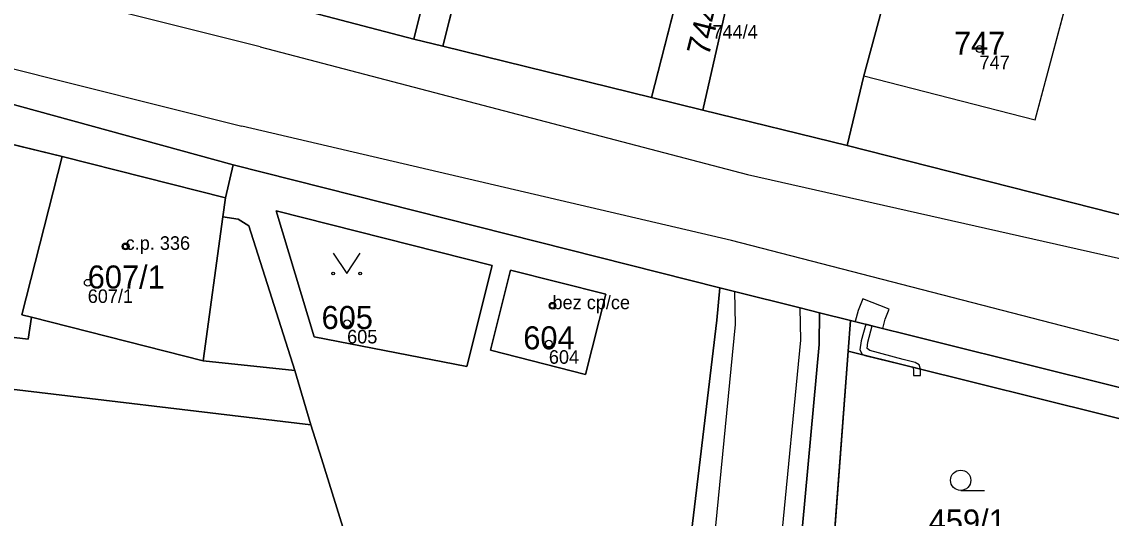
# Model space of a CAD drawing. Extents: x -603967 to -594699, y -1179315 to -1165625.
# Drawn here: x -598248.8 to -598168.4, y -1172272.3 to -1172235.7 of the extents above; entities that cross this region are included whole.
import ezdxf

# ---------------------------------------------------------------- set-up
doc = ezdxf.new("R2010")
doc.units = 0
for name, color, linetype in [('Definiční body', 7, 'Continuous'), ('Hranice parcel', 7, 'Continuous'), ('Parcelní čísla', 7, 'Continuous'), ('Polygon budovy', 7, 'Continuous'), ('Polygon parcely', 7, 'Continuous'), ('Vnitřní kresba', 7, 'Continuous'), ('Věcná břemena k části', 7, 'Continuous'), ('Značky budov', 7, 'Continuous'), ('Značky kultur', 7, 'Continuous')]:
    doc.layers.add(name, color=color, linetype=linetype)

msp = doc.modelspace()

# ---------------------------------------------------------------- linework, layer by layer
at = {"layer": 'Definiční body'}
for centre in [(-598178.09, -1172237.65994), (-598241.16, -1172252.22994), (-598243.96, -1172254.90994), (-598209.63, -1172256.60994), (-598224.8, -1172257.89994), (-598209.9, -1172259.39994)]:
    msp.add_circle(centre, 0.25, dxfattribs=at)
at = {"layer": 'Hranice parcel'}
for p, q in [((-598198.8, -1172227.49), (-598202.31, -1172241.23)), ((-598198.53, -1172242.16), (-598195.39, -1172228.4)), ((-598215.91, -1172230.22), (-598217.72, -1172237.46)), ((-598219.87, -1172236.93), (-598230.62, -1172234.12)), ((-598217.72, -1172237.46), (-598219.87, -1172236.93)), ((-598217.72, -1172237.46), (-598202.31, -1172241.23)), ((-598202.31, -1172241.23), (-598198.53, -1172242.16)), ((-598198.53, -1172242.16), (-598187.86, -1172244.77)), ((-598253.86, -1172243.64), (-598245.84, -1172245.6)), ((-598187.86, -1172244.77), (-598166.74, -1172250.14)), ((-598245.84, -1172245.6), (-598233.78, -1172248.64)), ((-598233.22, -1172246.2), (-598233.78, -1172248.64)), ((-598197.27, -1172255.28), (-598233.22, -1172246.2)), ((-598232.84, -1172250.21), (-598232.07, -1172250.7)), ((-598232.07, -1172250.7), (-598228.67, -1172261.38)), ((-598248.11, -1172257.46), (-598235.44, -1172260.68)), ((-598187.62, -1172257.69), (-598189.9, -1172257.12)), ((-598187.62, -1172257.69), (-598187.79, -1172259.97)), ((-598187.79, -1172259.97), (-598189.27, -1172279.58)), ((-598187.79, -1172259.97), (-598164.23, -1172265.81)), ((-598235.44, -1172260.68), (-598228.67, -1172261.38)), ((-598228.67, -1172261.38), (-598227.48, -1172265.39))]:
    msp.add_line(p, q, dxfattribs=at)
for points in [[(-598187.86, -1172244.77), (-598186.64, -1172239.63), (-598184.27, -1172230.87), (-598173.17, -1172211.68)], [(-598233.22, -1172246.2), (-598262.22, -1172238.25), (-598295.58, -1172230.95), (-598329.07, -1172222.19), (-598354.13, -1172216.53)], [(-598219.87, -1172236.93), (-598218.56, -1172231.67), (-598218.05, -1172229.68), (-598216.3, -1172222.79), (-598214.82, -1172220.18)], [(-598245.84, -1172245.6), (-598248.83, -1172257.28), (-598248.11, -1172257.46)], [(-598233.78, -1172248.64), (-598233.97, -1172250.05), (-598232.84, -1172250.21)], [(-598215.97, -1172261.09), (-598227.24, -1172258.89), (-598230.03, -1172249.59), (-598214.08, -1172253.64), (-598215.97, -1172261.09)], [(-598207.2, -1172261.67), (-598214.21, -1172259.88), (-598212.73, -1172253.99), (-598205.7, -1172255.75), (-598207.2, -1172261.67)], [(-598197.27, -1172255.28), (-598197.5, -1172257.68), (-598202.71, -1172301.27), (-598203.09, -1172311.78), (-598203.76, -1172315.82), (-598204.5, -1172318.52), (-598208.6, -1172325.98)], [(-598189.9, -1172257.12), (-598191.35, -1172256.76), (-598196.2, -1172255.55), (-598197.27, -1172255.28)], [(-598248.11, -1172257.46), (-598248.35, -1172259.08), (-598257.14, -1172258.05)], [(-598189.9, -1172257.12), (-598189.93, -1172259.47), (-598193.86, -1172302.03), (-598194.9, -1172313.74), (-598196.17, -1172318.03), (-598197.64, -1172321.62), (-598200.11, -1172325.95)], [(-598133.67, -1172271.05), (-598168.04, -1172262.57), (-598187.62, -1172257.69)], [(-598227.48, -1172265.39), (-598252.29, -1172262.45), (-598264.39, -1172261.06), (-598272.47, -1172262.37)], [(-598215.97, -1172302.17), (-598217.18, -1172298.45), (-598226.7, -1172267.87), (-598227.48, -1172265.39)]]:
    msp.add_lwpolyline(points, dxfattribs=at)
at = {"layer": 'Polygon budovy'}
for points in [[(-598186.64, -1172239.63), (-598173.98, -1172242.88), (-598166.08, -1172213.33), (-598172.7, -1172211.79), (-598175.43, -1172221.2), (-598176.37, -1172220.97), (-598179.33, -1172231.65), (-598184.27, -1172230.87)], [(-598248.83, -1172257.28), (-598248.11, -1172257.46), (-598235.44, -1172260.68), (-598233.97, -1172250.05), (-598233.78, -1172248.64), (-598245.84, -1172245.6)], [(-598212.73, -1172253.99), (-598214.21, -1172259.88), (-598207.2, -1172261.67), (-598205.7, -1172255.75)]]:
    msp.add_lwpolyline(points, close=True, dxfattribs=at)
at = {"layer": 'Polygon parcely'}
for points in [[(-598217.72, -1172237.46), (-598202.31, -1172241.23), (-598198.8, -1172227.49), (-598211.12, -1172224.13), (-598209.45, -1172217.18), (-598208.02, -1172217.6), (-598206.91, -1172213.75), (-598207.63, -1172213.55), (-598207.55, -1172213.26), (-598201.09, -1172214.92), (-598200.55, -1172212.64), (-598195.4, -1172213.85), (-598195.72, -1172215.27), (-598187.75, -1172202.92), (-598168.51, -1172171.97), (-598182.17, -1172163.97), (-598204.25, -1172201.77), (-598210.24, -1172212.01), (-598212.71, -1172216.41), (-598214.17, -1172223.33), (-598215.91, -1172230.22)], [(-598169.2, -1172204.81), (-598179.08, -1172199.01), (-598182.93, -1172205.76), (-598190.53, -1172218.76), (-598184.23, -1172220.42), (-598185.98, -1172227.61), (-598187.92, -1172227.14), (-598188.67, -1172230.2), (-598195.39, -1172228.4), (-598198.53, -1172242.16), (-598187.86, -1172244.77), (-598186.64, -1172239.63), (-598184.27, -1172230.87), (-598173.17, -1172211.68)], [(-598173.17, -1172211.68), (-598184.27, -1172230.87), (-598186.64, -1172239.63), (-598187.86, -1172244.77), (-598166.74, -1172250.14), (-598165.28, -1172245.04), (-598163.13, -1172236.55), (-598155.73, -1172224), (-598153.51, -1172220.14), (-598152.29, -1172218.03), (-598145.09, -1172205.5), (-598154.17, -1172200.59), (-598157.29, -1172206.36), (-598162.21, -1172215.46), (-598166.08, -1172213.33), (-598172.7, -1172211.79)], [(-598230.62, -1172234.12), (-598219.87, -1172236.93), (-598218.56, -1172231.67), (-598218.05, -1172229.68), (-598216.3, -1172222.79), (-598214.82, -1172220.18), (-598212.71, -1172216.41), (-598211.39, -1172211.46), (-598219.55, -1172207.52), (-598225.92, -1172218.59), (-598226.91, -1172220.56), (-598229.18, -1172228.9)], [(-598214.17, -1172223.33), (-598212.71, -1172216.41), (-598214.82, -1172220.18), (-598216.3, -1172222.79), (-598218.05, -1172229.68), (-598218.56, -1172231.67), (-598219.87, -1172236.93), (-598217.72, -1172237.46), (-598215.91, -1172230.22)], [(-598195.39, -1172228.4), (-598198.8, -1172227.49), (-598202.31, -1172241.23), (-598198.53, -1172242.16)], [(-598245.84, -1172245.6), (-598253.86, -1172243.64), (-598257.14, -1172258.05), (-598248.35, -1172259.08), (-598248.11, -1172257.46), (-598248.83, -1172257.28)], [(-598235.44, -1172260.68), (-598228.67, -1172261.38), (-598232.07, -1172250.7), (-598232.84, -1172250.21), (-598233.97, -1172250.05), (-598233.78, -1172248.64), (-598245.84, -1172245.6), (-598248.83, -1172257.28), (-598248.11, -1172257.46)], [(-598232.07, -1172250.7), (-598228.67, -1172261.38), (-598227.48, -1172265.39), (-598226.7, -1172267.87), (-598217.18, -1172298.45), (-598215.97, -1172302.17), (-598208.6, -1172325.98), (-598204.5, -1172318.52), (-598203.76, -1172315.82), (-598203.09, -1172311.78), (-598202.71, -1172301.27), (-598197.5, -1172257.68), (-598197.27, -1172255.28), (-598233.22, -1172246.2), (-598233.78, -1172248.64), (-598233.97, -1172250.05), (-598232.84, -1172250.21)], [(-598215.97, -1172261.09), (-598227.24, -1172258.89), (-598230.03, -1172249.59), (-598214.08, -1172253.64)], [(-598215.97, -1172261.09), (-598214.08, -1172253.64), (-598230.03, -1172249.59), (-598227.24, -1172258.89)], [(-598207.2, -1172261.67), (-598205.7, -1172255.75), (-598212.73, -1172253.99), (-598214.21, -1172259.88)], [(-598207.2, -1172261.67), (-598214.21, -1172259.88), (-598212.73, -1172253.99), (-598205.7, -1172255.75)], [(-598191.85, -1172316.63), (-598191.49, -1172309.99), (-598191.32, -1172306.82), (-598191, -1172301.28), (-598189.51, -1172282.59), (-598190.31, -1172282.53), (-598190.09, -1172280.16), (-598189.29, -1172280.15), (-598189.27, -1172279.58), (-598187.79, -1172259.97), (-598187.62, -1172257.69), (-598189.9, -1172257.12), (-598189.93, -1172259.47), (-598193.86, -1172302.03), (-598194.9, -1172313.74), (-598196.17, -1172318.03), (-598197.64, -1172321.62), (-598200.11, -1172325.95), (-598192.07, -1172320.73)], [(-598117.78, -1172277.34), (-598110.23, -1172279.22), (-598100.49, -1172281.67), (-598088.59, -1172284.27), (-598087.26, -1172281.76), (-598100.1, -1172279.2), (-598133.67, -1172271.05), (-598168.04, -1172262.57), (-598187.62, -1172257.69), (-598187.79, -1172259.97), (-598164.23, -1172265.81), (-598162.26, -1172266.3), (-598149.26, -1172269.52), (-598142.25, -1172271.27), (-598133.47, -1172273.44), (-598125.86, -1172275.37)], [(-598167.96, -1172281.09), (-598164.23, -1172265.81), (-598187.79, -1172259.97), (-598189.27, -1172279.58), (-598187.08, -1172279.72), (-598173.93, -1172280.64), (-598173.78, -1172280.68)], [(-598232.03, -1172306.97), (-598218.65, -1172302.82), (-598218.59, -1172303.01), (-598215.97, -1172302.17), (-598217.18, -1172298.45), (-598226.7, -1172267.87), (-598227.48, -1172265.39), (-598252.29, -1172262.45), (-598264.39, -1172261.06), (-598272.47, -1172262.37), (-598243.44, -1172317.29), (-598242.16, -1172318.04), (-598232.72, -1172312.96), (-598234.13, -1172309.94), (-598231.52, -1172308.6)]]:
    msp.add_lwpolyline(points, close=True, dxfattribs=at)
for points in [[(-598073.47, -1172274.19), (-598073.16, -1172271.95), (-598078.41, -1172271.53), (-598082.86, -1172271.28), (-598090.48, -1172269.19), (-598101.84, -1172266.14), (-598112.46, -1172263.54), (-598124.03, -1172260.73), (-598134.74, -1172258.12), (-598145.44, -1172255.45), (-598155.65, -1172252.91), (-598166.74, -1172250.14), (-598187.86, -1172244.77), (-598198.53, -1172242.16), (-598202.31, -1172241.23), (-598217.72, -1172237.46), (-598219.87, -1172236.93), (-598230.62, -1172234.12), (-598236.36, -1172232.63), (-598242.25, -1172231.09), (-598247.86, -1172229.53), (-598251.97, -1172228.39)], [(-598253.86, -1172243.64), (-598245.84, -1172245.6), (-598233.78, -1172248.64), (-598233.22, -1172246.2), (-598262.22, -1172238.25)], [(-598262.22, -1172238.25), (-598233.22, -1172246.2), (-598197.27, -1172255.28), (-598196.2, -1172255.55), (-598191.35, -1172256.76), (-598189.9, -1172257.12), (-598187.62, -1172257.69), (-598168.04, -1172262.57), (-598133.67, -1172271.05), (-598100.1, -1172279.2)], [(-598193.86, -1172302.03), (-598189.93, -1172259.47), (-598189.9, -1172257.12), (-598191.35, -1172256.76), (-598196.2, -1172255.55), (-598197.27, -1172255.28), (-598197.5, -1172257.68), (-598202.71, -1172301.27)], [(-598252.29, -1172262.45), (-598227.48, -1172265.39), (-598228.67, -1172261.38), (-598235.44, -1172260.68), (-598248.11, -1172257.46), (-598248.35, -1172259.08), (-598257.14, -1172258.05)]]:
    msp.add_lwpolyline(points, dxfattribs=at)
at = {"layer": 'Vnitřní kresba'}
for p, q in [((-598173.98, -1172242.88), (-598166.08, -1172213.33)), ((-598231.22, -1172237.49), (-598260.03, -1172230.28)), ((-598261.62, -1172236.06), (-598232.57, -1172243.36)), ((-598231.22, -1172237.49), (-598195.23, -1172246.93)), ((-598186.64, -1172239.63), (-598173.98, -1172242.88)), ((-598196.42, -1172251.78), (-598232.57, -1172243.36)), ((-598195.23, -1172246.93), (-598166.62, -1172253.36)), ((-598233.97, -1172250.05), (-598235.44, -1172260.68)), ((-598167.53, -1172259.24), (-598196.42, -1172251.78)), ((-598196.2, -1172255.55), (-598196.14, -1172258)), ((-598191.29, -1172259.14), (-598191.35, -1172256.76)), ((-598196.14, -1172258), (-598201.42, -1172312.07)), ((-598196.59, -1172313.42), (-598191.29, -1172259.14))]:
    msp.add_line(p, q, dxfattribs=at)
at = {"layer": 'Věcná břemena k části'}
for points in [[(-598187.27, -1172257.78), (-598186.5, -1172257.97), (-598186.01, -1172258.09), (-598185.23, -1172258.28), (-598185.06, -1172257.61), (-598184.77, -1172256.87), (-598186.71, -1172256.09), (-598187.06, -1172256.95)], [(-598186.01, -1172258.09), (-598186.5, -1172257.97), (-598186.83, -1172259.2), (-598186.92, -1172259.85), (-598186.76, -1172260.17), (-598186.57, -1172260.27), (-598183.02, -1172261.15), (-598182.45, -1172261.29), (-598182.55, -1172260.98), (-598182.84, -1172260.79), (-598183.74, -1172260.57), (-598186.2, -1172259.91), (-598186.4, -1172259.77), (-598186.33, -1172259.3)], [(-598183.02, -1172261.15), (-598182.96, -1172261.34), (-598182.96, -1172261.76), (-598182.46, -1172261.76), (-598182.46, -1172261.47), (-598182.45, -1172261.29)]]:
    msp.add_lwpolyline(points, close=True, dxfattribs=at)
at = {"layer": 'Značky budov'}
for centre in [(-598241.1668, -1172252.22916), (-598209.6368, -1172256.60916)]:
    msp.add_circle(centre, 0.175, dxfattribs=at)
at = {"layer": 'Značky kultur'}
msp.add_line((-598179.483, -1172270.24), (-598177.733, -1172270.24), dxfattribs=at)
msp.add_lwpolyline([(-598225.83, -1172252.729), (-598224.83, -1172254.23), (-598223.83, -1172252.729)], dxfattribs=at)
for centre, radius in [((-598225.83, -1172254.22946), 0.1), ((-598223.83, -1172254.22946), 0.1), ((-598179.48286, -1172269.48981), 0.75)]:
    msp.add_circle(centre, radius, dxfattribs=at)

# ---------------------------------------------------------------- texts
at = {"layer": 'Definiční body'}
for s, p in [('744/4', (-598197.82, -1172236.889)), ('747', (-598178.09, -1172239.149)), ('c.p. 336', (-598241.16, -1172252.48)), ('607/1', (-598243.96, -1172256.399)), ('bez cp/ce', (-598209.63, -1172256.86)), ('605', (-598224.8, -1172259.389)), ('604', (-598209.9, -1172260.889))]:
    msp.add_text(s, height=0.999996, dxfattribs=at).set_placement(p)
at = {"layer": 'Parcelní čísla'}
msp.add_text('744/4', height=1.699998, rotation=76, dxfattribs=at).set_placement((-598198.093, -1172238.254))
for s, p in [('747', (-598179.98, -1172238.085)), ('607/1', (-598243.96, -1172255.335)), ('605', (-598226.69, -1172258.325)), ('604', (-598211.79, -1172259.825)), ('459/1', (-598181.846, -1172273.345))]:
    msp.add_text(s, height=1.699998, dxfattribs=at).set_placement(p)

doc.saveas('drawing.dxf')
